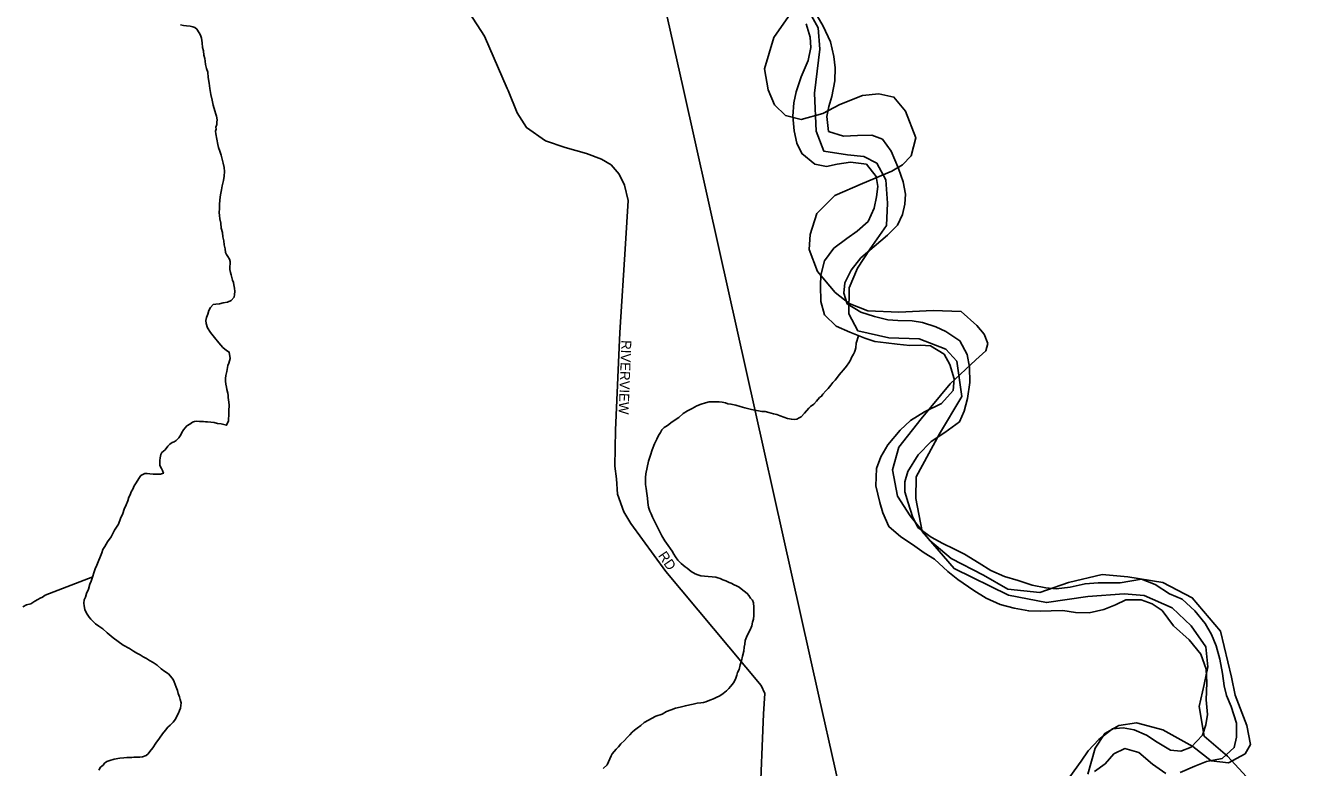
# Model space of a CAD drawing. Extents: x 2010165 to 2382125, y 1060529 to 1407316.
# Drawn here: x 2219461 to 2225862, y 1198951 to 1202703 of the extents above; entities that cross this region are included whole.
import ezdxf

# ---------------------------------------------------------------- set-up
doc = ezdxf.new("R2010")
doc.units = 0
for name, color, linetype in [('GM_X_Adjacent_County', 7, 'Continuous'), ('GM_X_City_Street', 7, 'Continuous'), ('GM_X_City_Street_Text', 7, 'Continuous'), ('GM_X_Corporation', 7, 'Continuous'), ('GM_X_County', 7, 'Continuous'), ('GM_X_Major_River', 7, 'Continuous'), ('GM_X_Minor_River', 7, 'Continuous'), ('GM_X_Rail_Line', 7, 'Continuous')]:
    doc.layers.add(name, color=color, linetype=linetype)

msp = doc.modelspace()

# ---------------------------------------------------------------- linework, layer by layer
at = {"layer": 'GM_X_Adjacent_County'}
msp.add_lwpolyline([(2224831.8, 1198917.6), (2224868.9, 1199050.1), (2224916.6, 1199124.2), (2224988.2, 1199164), (2225078.2, 1199177.2), (2225210.7, 1199142.8), (2225361.7, 1199058), (2225454.5, 1198986.5), (2225541.9, 1198975.9), (2225626.7, 1199020.9), (2225653.2, 1199068.6), (2225634.6, 1199164), (2225576.3, 1199317.6), (2225558.1, 1199409.1), (2225502.1, 1199640.9), (2225359.1, 1199810.4), (2225210.7, 1199887.3), (2225033.2, 1199916.4), (2224903.4, 1199927), (2224733.8, 1199887.3), (2224588.1, 1199836.9), (2224426.5, 1199852.8), (2224304.6, 1199924.4), (2224140.3, 1200009.2), (2224033.1, 1200099.2), (2223933.7, 1200223.8), (2223870.1, 1200324.4), (2223843.6, 1200456.9), (2223875.4, 1200570.8), (2223989.3, 1200713.9), (2224135, 1200891.4), (2224264.9, 1201013.3), (2224315.2, 1201058.3), (2224325.8, 1201095.4), (2224307.2, 1201143.1), (2224270.1, 1201185.5), (2224190.7, 1201257), (2224050.2, 1201262.3), (2223875.4, 1201254.4), (2223719.1, 1201259.7), (2223624.4, 1201296.8), (2223554.8, 1201352.4), (2223464.7, 1201458.4), (2223422.3, 1201569.7), (2223427.6, 1201646.5), (2223462.1, 1201752.5), (2223552.1, 1201842.6), (2223692.6, 1201903.5), (2223840.9, 1201967.1), (2223893.9, 1201998.9), (2223939, 1202043.9), (2223962.8, 1202134), (2223909.8, 1202269.1), (2223851.5, 1202340.7), (2223774.7, 1202356.6), (2223692.6, 1202348.6), (2223578.6, 1202303.6), (2223491.2, 1202258.5), (2223382.6, 1202226.8), (2223303.1, 1202247.9), (2223247.5, 1202300.9), (2223215.7, 1202377.8), (2223197.1, 1202483.7), (2223244.8, 1202642.7), (2223353.4, 1202799)], dxfattribs=at)
at = {"layer": 'GM_X_City_Street'}
for points in [[(2221896.6, 1202383.6), (2221781.3, 1202648.2), (2221705, 1202767.6), (2221472.1, 1203121.8), (2221282.2, 1203403.7), (2220879, 1204002.5), (2220732.2, 1204233.5), (2220675.5, 1204356.8), (2220650.1, 1204415.5), (2220497.4, 1204853.9), (2220436.7, 1205059.4), (2220397.6, 1205218), (2220374.1, 1205290.4), (2220333, 1205349.1), (2220254.7, 1205431.3), (2219785, 1205951.1)], [(2222493.9, 1201599.3), (2222507.4, 1201818.4), (2222489.8, 1201894.7), (2222462.4, 1201951.4), (2222421.3, 1201998.4), (2222372.4, 1202027.8), (2222298, 1202055.2), (2222190.3, 1202086.5), (2222090.5, 1202119.7), (2221994.6, 1202186.3), (2221947.7, 1202260.7), (2221900.7, 1202374.2), (2221896.6, 1202383.6)], [(2223172.9, 1198769.1), (2223192.4, 1199223.1), (2223198.3, 1199326.9), (2223180.7, 1199366), (2222699.2, 1199943.4), (2222521.1, 1200186.1), (2222485.9, 1200244.8), (2222454.5, 1200332.9), (2222448.7, 1200411.1), (2222440.9, 1200475.7), (2222444.8, 1200657.7), (2222466.3, 1201150.9), (2222493.9, 1201599.3)]]:
    msp.add_lwpolyline(points, dxfattribs=at)
at = {"layer": 'GM_X_Corporation'}
msp.add_lwpolyline([(2223400.7, 1202812.6), (2223468.4, 1202690), (2223476.1, 1202583.6), (2223449.3, 1202360.8), (2223458.7, 1202168), (2223496.5, 1202067.5), (2223616.8, 1202049.2), (2223699, 1202041), (2223765, 1202006.7), (2223810.9, 1201922.3), (2223818.5, 1201803.8), (2223814.2, 1201691.3), (2223731.6, 1201573), (2223667.1, 1201476.8), (2223624.7, 1201376.5), (2223624.2, 1201246), (2223668.1, 1201159.5), (2223826.4, 1201123.1), (2223978.8, 1201118.7), (2224113, 1201066.3), (2224168.9, 1201005.9), (2224194.4, 1200827.1), (2224081.5, 1200638.6), (2223964.5, 1200422), (2223962.1, 1200311.6), (2223993.7, 1200144.8), (2224155.5, 1199957.8), (2224429.8, 1199822.7), (2224622.2, 1199786.1), (2224830.9, 1199815.8), (2225015.4, 1199829.5), (2225115.6, 1199821.2), (2225257.8, 1199758.7), (2225353.8, 1199668.1), (2225427.6, 1199561.6), (2225437.3, 1199461.2), (2225419, 1199370.8), (2225394.6, 1199260.4), (2225420.1, 1199109.8), (2225538.1, 1199009.1), (2225861.9, 1198655.1)], dxfattribs=at)
at = {"layer": 'GM_X_County'}
msp.add_lwpolyline([(2223353.4, 1202799), (2223244.8, 1202642.7), (2223197.1, 1202483.7), (2223215.7, 1202377.8), (2223247.5, 1202300.9), (2223303.1, 1202247.9), (2223382.6, 1202226.8), (2223491.2, 1202258.5), (2223578.6, 1202303.6), (2223692.6, 1202348.6), (2223774.7, 1202356.6), (2223851.5, 1202340.7), (2223909.8, 1202269.1), (2223962.8, 1202134), (2223939, 1202043.9), (2223893.9, 1201998.9), (2223840.9, 1201967.1), (2223692.6, 1201903.5), (2223552.1, 1201842.6), (2223462.1, 1201752.5), (2223427.6, 1201646.5), (2223422.3, 1201569.7), (2223464.7, 1201458.4), (2223554.8, 1201352.4), (2223624.4, 1201296.8), (2223719.1, 1201259.7), (2223875.4, 1201254.4), (2224050.2, 1201262.3), (2224190.7, 1201257), (2224270.1, 1201185.5), (2224307.2, 1201143.1), (2224325.8, 1201095.4), (2224315.2, 1201058.3), (2224264.9, 1201013.3), (2224135, 1200891.4), (2223989.3, 1200713.9), (2223875.4, 1200570.8), (2223843.6, 1200456.9), (2223870.1, 1200324.4), (2223933.7, 1200223.8), (2224033.1, 1200099.2), (2224140.3, 1200009.2), (2224304.6, 1199924.4), (2224426.5, 1199852.8), (2224588.1, 1199836.9), (2224733.8, 1199887.3), (2224903.4, 1199927), (2225033.2, 1199916.4), (2225210.7, 1199887.3), (2225359.1, 1199810.4), (2225502.1, 1199640.9), (2225558.1, 1199409.1), (2225576.3, 1199317.6), (2225634.6, 1199164), (2225653.2, 1199068.6), (2225626.7, 1199020.9), (2225541.9, 1198975.9), (2225454.5, 1198986.5), (2225361.7, 1199058), (2225210.7, 1199142.8), (2225078.2, 1199177.2), (2224988.2, 1199164), (2224916.6, 1199124.2), (2224868.9, 1199050.1), (2224831.8, 1198917.6)], dxfattribs=at)
at = {"layer": 'GM_X_Major_River'}
for points in [[(2223451.5, 1202772.2), (2223494.2, 1202698.4), (2223530.9, 1202620.5), (2223547.5, 1202546.5), (2223554, 1202488.3), (2223552.6, 1202422.1), (2223537.3, 1202343.8), (2223521.7, 1202293.4), (2223512.1, 1202243.2), (2223520.8, 1202167.1), (2223597.1, 1202143.7), (2223667.1, 1202146.4), (2223739.1, 1202149.1), (2223793.3, 1202127.5), (2223837.9, 1202067.8), (2223874.7, 1201979.9), (2223897.3, 1201911.9)], [(2223408, 1202711.6), (2223428.6, 1202643.6), (2223431.1, 1202591.5), (2223417.6, 1202525.2), (2223382.3, 1202442.6), (2223356.9, 1202368.1), (2223345.4, 1202311.8), (2223340, 1202243.6), (2223346.7, 1202169.4), (2223361.2, 1202107.4), (2223385.7, 1202055.4), (2223452.2, 1202001.9), (2223510.3, 1201990.4), (2223564.3, 1202001), (2223632.2, 1202011.7), (2223712.4, 1202002.4), (2223761, 1201938.7), (2223769.4, 1201888.6), (2223763.9, 1201836.4), (2223752.3, 1201780.1), (2223720.9, 1201711.6), (2223665.3, 1201662.9), (2223613.6, 1201626.3), (2223547.9, 1201577.6), (2223500.5, 1201512.9), (2223481.1, 1201440.5), (2223479.5, 1201388.3), (2223482.2, 1201308.1), (2223500.8, 1201240.1), (2223559.4, 1201182.5), (2223627.7, 1201153), (2223704, 1201121.7), (2223754.2, 1201106.1), (2223812.3, 1201098.6), (2223868.4, 1201091.1), (2223932.5, 1201085.7), (2223986.5, 1201086.2), (2224036.6, 1201082.7), (2224105, 1201041.2), (2224133.5, 1200989.3), (2224156.1, 1200917.3), (2224150.6, 1200857.1), (2224091.2, 1200792.3), (2224005.5, 1200749.4), (2223935.8, 1200706.6), (2223882.2, 1200658), (2223820.8, 1200583.1), (2223785.3, 1200522.6), (2223763.8, 1200464.2), (2223760.5, 1200375.9), (2223779.3, 1200291.9), (2223795.7, 1200239.9), (2223826.4, 1200169.9), (2223886.8, 1200118.4), (2223945.2, 1200078.8), (2224003.6, 1200037.2), (2224055.9, 1200005.6), (2224124.6, 1199942.1), (2224174.9, 1199902.4), (2224255.5, 1199847.1), (2224317.9, 1199807.5), (2224388.2, 1199776.1), (2224458.4, 1199756.7), (2224532.6, 1199743.4), (2224594.6, 1199742), (2224646.7, 1199744.5), (2224704.7, 1199745), (2224768.8, 1199735.6), (2224838.9, 1199734.3), (2224912.8, 1199751), (2224970.6, 1199773.6), (2225024.4, 1199800.2), (2225100.5, 1199798.9), (2225156.7, 1199779.4), (2225207.1, 1199745.8), (2225263.8, 1199668.1), (2225344.4, 1199596.6), (2225403.1, 1199525), (2225429.8, 1199449), (2225432.4, 1199380.8), (2225429.1, 1199294.5), (2225435.8, 1199220.4)], [(2223897.3, 1201911.9), (2223909.8, 1201849.8), (2223906.3, 1201799.6), (2223894.7, 1201747.4), (2223869.2, 1201693), (2223819.6, 1201642.3), (2223684.5, 1201528.7), (2223635, 1201466), (2223603.5, 1201401.6), (2223598, 1201349.3), (2223614.4, 1201295.3), (2223684.9, 1201253.9), (2223753.1, 1201232.5), (2223821.3, 1201215.1), (2223871.4, 1201211.5), (2223943.4, 1201210.2), (2223995.5, 1201200.7), (2224063.8, 1201179.3), (2224114, 1201155.7), (2224184.5, 1201108.2), (2224221.1, 1201040.3), (2224233.7, 1200976.3), (2224234.3, 1200898), (2224223, 1200817.7), (2224205.6, 1200753.3), (2224182, 1200698.9), (2224108.4, 1200646.1), (2224038.8, 1200599.3), (2223973.3, 1200532.4), (2223922, 1200447.7), (2223906.5, 1200395.4), (2223906.9, 1200345.2), (2223923.4, 1200289.2), (2223946, 1200221.2), (2223972.5, 1200165.3), (2224039, 1200115.8), (2224099.3, 1200084.3), (2224153.6, 1200056.7), (2224207.8, 1200031.1), (2224282.3, 1199985.7), (2224340.7, 1199948.2), (2224411, 1199916.7), (2224479.2, 1199897.3), (2224549.5, 1199873.9), (2224619.6, 1199860.6), (2224671.7, 1199855), (2224741.7, 1199863.7), (2224817.6, 1199880.5), (2224883.6, 1199885.1), (2224995.7, 1199886.2), (2225103.6, 1199903.3), (2225171.9, 1199877.9), (2225244.4, 1199830.4), (2225308.6, 1199802.9), (2225373.2, 1199743.4), (2225423.8, 1199679.7), (2225456.3, 1199623.8), (2225480.8, 1199567.9), (2225499.4, 1199499.8), (2225512, 1199427.7), (2225520.6, 1199365.6), (2225533, 1199315.6), (2225555.5, 1199259.6), (2225582.3, 1199175.6), (2225582.9, 1199105.4), (2225571.3, 1199053.1), (2225509.7, 1198998.4), (2225431.8, 1198981.6), (2225372, 1198959), (2225298.2, 1198926.2)], [(2225435.8, 1199220.4), (2225428.2, 1199168.1), (2225410.7, 1199115.8), (2225353.1, 1199055.1), (2225301.3, 1199034.5), (2225249.2, 1199040.1), (2225182.8, 1199079.5), (2225128.5, 1199115.1), (2225066.2, 1199142.6), (2225010.1, 1199152.1), (2224956.1, 1199147.6), (2224886.5, 1199092.8), (2224832.9, 1199036.1), (2224797.4, 1198983.6), (2224718.2, 1198874.5)], [(2225226.2, 1198921.5), (2225157.7, 1198969), (2225089.2, 1199028.5), (2225019, 1199047.9), (2224963.1, 1199021.3), (2224919.6, 1198970.7), (2224865.9, 1198932.1)]]:
    msp.add_lwpolyline(points, dxfattribs=at)
at = {"layer": 'GM_X_Minor_River'}
for points in [[(2220245.5, 1202705.2), (2220259.6, 1202703.4), (2220275.6, 1202701.6), (2220293.7, 1202699.8), (2220307.8, 1202695.9), (2220317.8, 1202692.1), (2220328, 1202684.1), (2220340.2, 1202666.2), (2220346.4, 1202654.3), (2220350.6, 1202638.3), (2220354.9, 1202614.2), (2220357.2, 1202592.2), (2220361.5, 1202574.1), (2220363.7, 1202552.1), (2220368, 1202536.1), (2220370.1, 1202522.1), (2220372.4, 1202506), (2220376.6, 1202486), (2220382.9, 1202466)], [(2220382.9, 1202466), (2220385.2, 1202439.9), (2220389.6, 1202411.9), (2220394, 1202383.8), (2220398.4, 1202353.8), (2220404.8, 1202325.7), (2220411.1, 1202299.7), (2220419.5, 1202271.7), (2220423.7, 1202253.7), (2220427.9, 1202243.7), (2220430.1, 1202225.7), (2220428.3, 1202213.6), (2220428.4, 1202201.6), (2220424.6, 1202189.4), (2220424.7, 1202179.4), (2220422.8, 1202169.3), (2220423, 1202155.3), (2220433.7, 1202101.2), (2220438, 1202085.2), (2220444.2, 1202067.2), (2220450.5, 1202047.2), (2220461, 1202007.2), (2220465.3, 1201985.2), (2220467.6, 1201965.1), (2220465.9, 1201941), (2220462.2, 1201918.9), (2220456.5, 1201892.7), (2220452.8, 1201872.6), (2220449, 1201854.4), (2220445.2, 1201836.3), (2220443.4, 1201818.2), (2220441.7, 1201800.1), (2220442, 1201778.1), (2220440.2, 1201758), (2220442.4, 1201741.9), (2220444.7, 1201725.9), (2220449, 1201703.9), (2220451.3, 1201677.8), (2220457.6, 1201655.8), (2220459.9, 1201633.7), (2220464.1, 1201613.7), (2220466.4, 1201593.6), (2220470.7, 1201573.6), (2220472.9, 1201555.6), (2220477.1, 1201545.6), (2220485.2, 1201535.6), (2220493.4, 1201521.7), (2220495.6, 1201509.7), (2220495.7, 1201497.6), (2220493.9, 1201483.6), (2220494.1, 1201469.5), (2220498.3, 1201453.5), (2220500.5, 1201441.5), (2220504.6, 1201429.5), (2220508.8, 1201415.5), (2220513, 1201403.5), (2220515.1, 1201391.5), (2220517.4, 1201375.4), (2220519.6, 1201357.4), (2220517.8, 1201343.3), (2220515.9, 1201329.2), (2220502.1, 1201313), (2220482.2, 1201304.7), (2220460.2, 1201300.4), (2220442.2, 1201296.2), (2220424.2, 1201293.9), (2220410.2, 1201291.7), (2220396.4, 1201277.5), (2220388.6, 1201261.3), (2220382.8, 1201243.2), (2220377, 1201227.1), (2220373.2, 1201210.9), (2220375.4, 1201196.9), (2220381.7, 1201174.9), (2220396, 1201151), (2220416.4, 1201125.2), (2220438.8, 1201099.3), (2220459.1, 1201075.5), (2220477.4, 1201059.7), (2220491.5, 1201051.8), (2220495.9, 1201019.8), (2220490.2, 1200995.6), (2220484.4, 1200983.5), (2220482.5, 1200973.4), (2220480.6, 1200963.3), (2220478.8, 1200953.3), (2220475, 1200933.2), (2220473.2, 1200919.1), (2220473.4, 1200905), (2220473.6, 1200889), (2220477.8, 1200875), (2220480, 1200862.9), (2220484.2, 1200844.9), (2220486.4, 1200832.9), (2220486.5, 1200822.9), (2220488.6, 1200810.8), (2220488.8, 1200798.8), (2220491, 1200782.8), (2220489.4, 1200754.6), (2220489.6, 1200740.6), (2220488, 1200704.4)], [(2223672.3, 1201134.7), (2223660.7, 1201096.2), (2223659, 1201074.1), (2223655.1, 1201062), (2223651.3, 1201052), (2223647.4, 1201041.9), (2223637.6, 1201023.7), (2223631.8, 1201011.6), (2223623.9, 1200997.4), (2223612.1, 1200981.2), (2223596.3, 1200962.9), (2223584.5, 1200948.7), (2223574.6, 1200936.5), (2223566.8, 1200924.4), (2223554.9, 1200910.2), (2223543.1, 1200898), (2223533.2, 1200883.8), (2223519.4, 1200867.6), (2223507.6, 1200855.4), (2223491.7, 1200839.1), (2223485.9, 1200829), (2223475.9, 1200822.8), (2223460.1, 1200804.6), (2223446.3, 1200788.3), (2223430.4, 1200776.1), (2223420.5, 1200767.9), (2223398.8, 1200743.5), (2223383, 1200725.3), (2223373.1, 1200719.1), (2223361.1, 1200712.9), (2223347.1, 1200710.8), (2223333.1, 1200712.6), (2223313, 1200716.3), (2223294.9, 1200722.1), (2223276.8, 1200729.9), (2223258.7, 1200735.7), (2223242.6, 1200739.5), (2223230.5, 1200743.4), (2223218.4, 1200747.3), (2223200.4, 1200751.1), (2223184.3, 1200750.8), (2223166.2, 1200754.6), (2223146.2, 1200758.4), (2223124, 1200764.1), (2223097.9, 1200769.8), (2223073.8, 1200777.5), (2223051.7, 1200783.3), (2223027.5, 1200789), (2223011.5, 1200790.8), (2222999.4, 1200794.7), (2222983.3, 1200798.5), (2222967.3, 1200800.3), (2222949.3, 1200800.1), (2222933.2, 1200799.8), (2222917.2, 1200799.6), (2222899.2, 1200795.4), (2222877.3, 1200789.1), (2222855.3, 1200780.8), (2222831.5, 1200766.4), (2222807.6, 1200754.1), (2222785.7, 1200741.7), (2222763.9, 1200721.4), (2222730.2, 1200698.9), (2222706.4, 1200680.5), (2222690.5, 1200670.2), (2222678.6, 1200658.1), (2222670.8, 1200645.9), (2222660.9, 1200629.7), (2222653.2, 1200611.5), (2222641.5, 1200587.3), (2222629.8, 1200557), (2222620.2, 1200530.8), (2222610.5, 1200500.6), (2222597.4, 1200436.1), (2222595.6, 1200418.1), (2222595.8, 1200400), (2222596.1, 1200381.9), (2222598.3, 1200361.9), (2222602.6, 1200337.8), (2222605, 1200313.8), (2222607.2, 1200291.7), (2222611.6, 1200267.7), (2222617.8, 1200247.7), (2222624, 1200233.7), (2222630.3, 1200217.7), (2222640.5, 1200197.8), (2222650.8, 1200177.8), (2222663.1, 1200153.9), (2222677.6, 1200123.9), (2222693.9, 1200098), (2222710.3, 1200074.1), (2222722.5, 1200058.2), (2222730.7, 1200046.3), (2222738.9, 1200030.3), (2222747.1, 1200016.4), (2222759.3, 1200000.5), (2222775.6, 1199982.6), (2222795.8, 1199966.8), (2222805.9, 1199958.9), (2222816.1, 1199951), (2222826.2, 1199943.1)], [(2220488, 1200704.4), (2220478.3, 1200682.2), (2220450.1, 1200689.9), (2220432.1, 1200691.7), (2220416, 1200695.5), (2220397.9, 1200697.2), (2220381.9, 1200699.1), (2220371.9, 1200698.9), (2220361.8, 1200700.8), (2220351.8, 1200700.7), (2220341.8, 1200700.6), (2220325.8, 1200702.3), (2220315.8, 1200700.2), (2220305.8, 1200698.1), (2220291.9, 1200687.9), (2220278, 1200679.7), (2220268.1, 1200669.5), (2220260.2, 1200659.3), (2220252.4, 1200645.2), (2220246.5, 1200633.1), (2220236.7, 1200618.9), (2220222.8, 1200604.7), (2220212.9, 1200598.5), (2220202.9, 1200594.4), (2220191, 1200586.2), (2220181.1, 1200576), (2220167.3, 1200557.8), (2220151.5, 1200543.5), (2220145.6, 1200533.4), (2220141.8, 1200517.3), (2220140, 1200503.2), (2220140.2, 1200489.1), (2220140.3, 1200479.1), (2220148.5, 1200463.2), (2220154.7, 1200453.2), (2220158.9, 1200439.2), (2220144.9, 1200435), (2220124.9, 1200434.8), (2220106.8, 1200434.5), (2220090.8, 1200436.3), (2220076.7, 1200438.1), (2220064.7, 1200438), (2220044.8, 1200427.7), (2220035, 1200413.5), (2220021.3, 1200391.3), (2220011.4, 1200375.1), (2220003.6, 1200358.9), (2219995.8, 1200344.8), (2219990, 1200330.6), (2219984.1, 1200318.5), (2219978.4, 1200300.4), (2219970.6, 1200280.2), (2219960.9, 1200258), (2219953.1, 1200235.8), (2219941.4, 1200211.5), (2219931.8, 1200181.3), (2219912.2, 1200150.9), (2219894.6, 1200118.6), (2219876.9, 1200092.2), (2219863.1, 1200070), (2219853.3, 1200053.8), (2219847.5, 1200037.7), (2219822.3, 1199975.1), (2219814.5, 1199956.9), (2219808.7, 1199940.8), (2219801, 1199914.6), (2219793.3, 1199894.4), (2219787.5, 1199878.3), (2219779.8, 1199854.1), (2219770.1, 1199831.9), (2219764.3, 1199813.7), (2219758.5, 1199799.6), (2219756.7, 1199783.5), (2219758.9, 1199769.5), (2219761.1, 1199751.4), (2219767.3, 1199739.5), (2219773.4, 1199727.5), (2219783.6, 1199711.6), (2219791.8, 1199701.6), (2219801.9, 1199691.7), (2219816.2, 1199677.8), (2219832.3, 1199666), (2219852.6, 1199652.2), (2219874.8, 1199632.4), (2219905.2, 1199606.7), (2219955.8, 1199571.2), (2219988.1, 1199553.5), (2220008.3, 1199539.7), (2220024.4, 1199529.9), (2220040.6, 1199522.1), (2220056.7, 1199512.2), (2220072.9, 1199502.4), (2220089, 1199492.6), (2220107.2, 1199482.8), (2220127.4, 1199469), (2220147.7, 1199451.1), (2220165.9, 1199437.3), (2220184.1, 1199425.5), (2220194.3, 1199413.6), (2220208.5, 1199397.7), (2220212.7, 1199385.7)], [(2222826.2, 1199943.1), (2222846.4, 1199931.3), (2222860.5, 1199925.5), (2222874.5, 1199921.6), (2222894.6, 1199919.9), (2222912.7, 1199918.1), (2222932.7, 1199916.3), (2222950.8, 1199914.6), (2222960.8, 1199910.7), (2222972.9, 1199906.8), (2222987, 1199901), (2223001.1, 1199895.1), (2223019.2, 1199887.3), (2223029.3, 1199883.4), (2223043.4, 1199875.6), (2223055.6, 1199869.7), (2223069.6, 1199863.9), (2223079.8, 1199856), (2223110.1, 1199832.3), (2223118.3, 1199822.3), (2223126.5, 1199808.4), (2223136.6, 1199798.5), (2223140.8, 1199784.5), (2223143.1, 1199762.4), (2223143.4, 1199740.3), (2223143.7, 1199720.3), (2223141.9, 1199702.2), (2223136.1, 1199686), (2223132.3, 1199667.9), (2223124.6, 1199647.7), (2223114.8, 1199629.5), (2223107, 1199611.4), (2223099.2, 1199593.2), (2223097.5, 1199575.1), (2223093.6, 1199561), (2223091.9, 1199540.9), (2223086.2, 1199514.7), (2223080.5, 1199490.6), (2223074.8, 1199470.4), (2223069.1, 1199448.2), (2223061.2, 1199432.1), (2223057.4, 1199418), (2223051.6, 1199403.8), (2223043.8, 1199385.7), (2223036, 1199373.5), (2223026.1, 1199361.3), (2223016.2, 1199351.2), (2223004.3, 1199339), (2222988.5, 1199326.7), (2222970.6, 1199314.5), (2222952.7, 1199306.2), (2222938.7, 1199300), (2222920.8, 1199291.7), (2222900.9, 1199283.4), (2222888.9, 1199281.3), (2222874.9, 1199279.1), (2222856.9, 1199276.9), (2222836.9, 1199272.6), (2222818.9, 1199268.3), (2222797, 1199264.1), (2222771, 1199257.7), (2222747, 1199251.4), (2222725.1, 1199243.1), (2222701.1, 1199234.7), (2222679.3, 1199222.4), (2222647.4, 1199211.9), (2222589.7, 1199179.1), (2222571.8, 1199164.8), (2222554, 1199150.5), (2222540.1, 1199140.3), (2222528.2, 1199130.1), (2222516.3, 1199117.9), (2222502.5, 1199103.7), (2222488.7, 1199089.4), (2222470.9, 1199071.1), (2222459, 1199056.9), (2222447.2, 1199044.7), (2222437.3, 1199032.6), (2222427.4, 1199020.4), (2222421.6, 1199010.3), (2222402.1, 1198965.9), (2222382.3, 1198947.5)], [(2219801.3, 1199915.5), (2219561.8, 1199823.2), (2219547.9, 1199813), (2219535.9, 1199808.8), (2219524, 1199800.6), (2219508.1, 1199792.4), (2219488.2, 1199780.1), (2219466.3, 1199773.8), (2219448.4, 1199763.5)], [(2220212.7, 1199385.7), (2220218.9, 1199371.7), (2220223.1, 1199357.7), (2220229.3, 1199341.8), (2220233.5, 1199325.7), (2220239.7, 1199309.8), (2220243.9, 1199295.8), (2220248.1, 1199279.7), (2220244.5, 1199251.6), (2220240.6, 1199239.5), (2220234.8, 1199227.4), (2220228.9, 1199215.2), (2220219.1, 1199197.1), (2220207.3, 1199180.8), (2220193.5, 1199166.6), (2220181.6, 1199156.4), (2220169.8, 1199140.2), (2220154, 1199121.9), (2220138.3, 1199099.6), (2220120.5, 1199075.3), (2220104.8, 1199051), (2220091, 1199032.8), (2220081.2, 1199020.6), (2220071.3, 1199012.4), (2220053.3, 1199006.2), (2220039.3, 1199004), (2220019.3, 1199003.7), (2220009.3, 1199003.6), (2219999.2, 1199003.5), (2219985.2, 1199003.3), (2219973.2, 1199003.2), (2219959.2, 1199001), (2219939.2, 1198998.7), (2219909.2, 1198994.3), (2219887.2, 1198988), (2219873.3, 1198981.8), (2219861.4, 1198973.6), (2219853.5, 1198963.5), (2219841.6, 1198953.3), (2219831.8, 1198939.1)]]:
    msp.add_lwpolyline(points, dxfattribs=at)
at = {"layer": 'GM_X_Rail_Line'}
msp.add_lwpolyline([(2224553.3, 1195434.3), (2224465.3, 1195685.2), (2224356.9, 1196003.8), (2224257.2, 1196313), (2224156.6, 1196633.1), (2224096.6, 1196837.8), (2223972.8, 1197258.3), (2223872.6, 1197626.9), (2223806.5, 1197878.4), (2223746.1, 1198113.3), (2223624.3, 1198630.6), (2223554.1, 1198945), (2223472.5, 1199312.1), (2222967.6, 1201570.3), (2222786.9, 1202378.8), (2222625.3, 1203100)], dxfattribs=at)

# ---------------------------------------------------------------- texts
at = {"layer": 'GM_X_City_Street_Text'}
for s, rotation, p in [('RIVERVIEW', 267.79858, (2222474.3, 1201112.9)), ('RD', 304.51433, (2222657.5, 1200023))]:
    msp.add_text(s, height=50, rotation=rotation, dxfattribs=at).set_placement(p)

doc.saveas('drawing.dxf')
